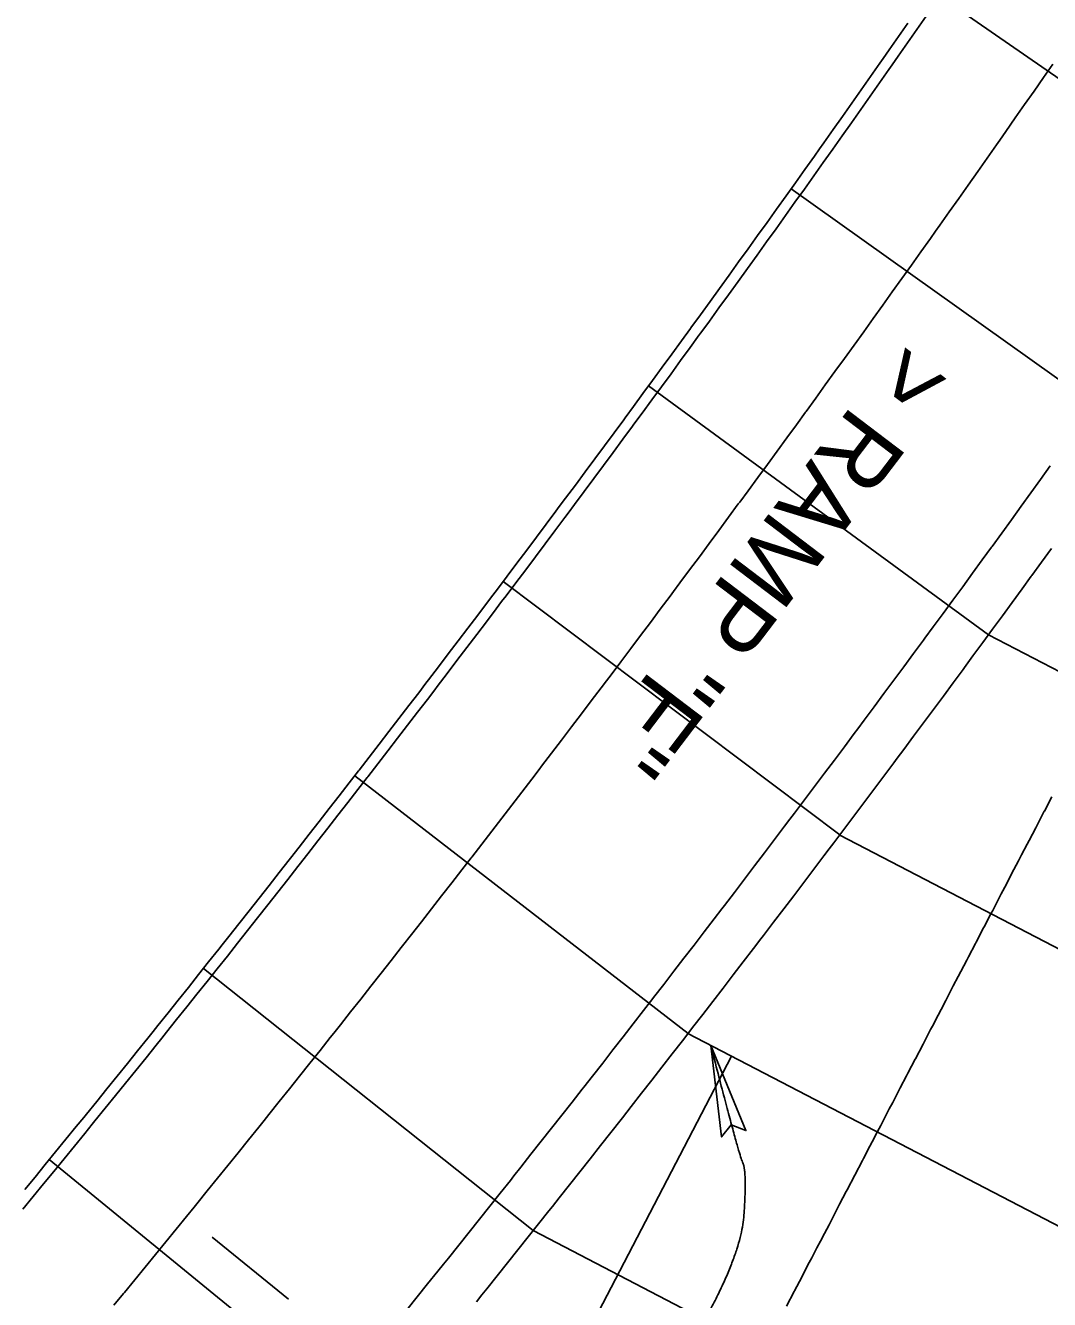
# Model space of a CAD drawing. Extents: x 2145147 to 2158018, y 137519 to 148068.
# Drawn here: x 2150427.2 to 2150489.6, y 143886.4 to 143964 of the extents above; entities that cross this region are included whole.
import ezdxf

# ---------------------------------------------------------------- set-up
doc = ezdxf.new("R2010")
doc.units = 0
for name, color, linetype in [('PR_Align_Ramp_F', 7, 'Continuous'), ('PR_Align_Ramp_F_Label', 7, 'Continuous'), ('PR_Dimensions', 7, 'Continuous'), ('PR_Joint_Contraction', 7, 'Continuous'), ('PR_Joint_Long', 7, 'Continuous'), ('PR_Road_Concrete', 7, 'Continuous')]:
    doc.layers.add(name, color=color, linetype=linetype)

msp = doc.modelspace()

# ---------------------------------------------------------------- linework, layer by layer
at = {"layer": 'PR_Align_Ramp_F'}
msp.add_lwpolyline([(2150443.256, 143886.371), (2150438.6, 143890.156)], dxfattribs=at)
at = {"layer": 'PR_Dimensions'}
msp.add_lwpolyline([(2150468.976, 143901.836), (2150469.629, 143896.26), (2150470.211, 143897.005), (2150471.112, 143896.649)], close=True, dxfattribs=at)
msp.add_open_spline([(2150468.143, 143884.29), (2150470.819, 143888.915), (2150471.175, 143894.152), (2150470.668, 143895.218), (2150468.976, 143901.836)], degree=2, dxfattribs=at)
at = {"layer": 'PR_Joint_Contraction'}
for p, q in [((2150503.472, 143951.523), (2150482.38, 143966.149)), ((2150494.767, 143939.143), (2150473.867, 143954.043)), ((2150485.885, 143926.855), (2150465.182, 143942.027)), ((2150476.825, 143914.661), (2150456.322, 143930.103)), ((2150485.885, 143926.856), (2150509.818, 143914.4)), ((2150467.586, 143902.559), (2150447.287, 143918.268)), ((2150476.826, 143914.66), (2150502.893, 143901.094)), ((2150458.166, 143890.552), (2150438.076, 143906.526)), ((2150467.585, 143902.56), (2150495.968, 143887.788)), ((2150448.565, 143878.639), (2150428.687, 143894.877)), ((2150458.166, 143890.552), (2150489.043, 143874.482))]:
    msp.add_line(p, q, dxfattribs=at)
at = {"layer": 'PR_Joint_Long'}
msp.add_line((2150449.468, 143861.259), (2150470.243, 143901.177), dxfattribs=at)
for points in [[(2150489.798, 143961.637), (2150489.229, 143960.817), (2150488.659, 143959.997), (2150488.089, 143959.178), (2150487.518, 143958.359), (2150486.946, 143957.541), (2150486.575, 143957.01), (2150486.374, 143956.723), (2150485.801, 143955.906), (2150485.227, 143955.089), (2150484.652, 143954.272), (2150484.077, 143953.457), (2150483.501, 143952.641), (2150482.924, 143951.826), (2150482.665, 143951.46), (2150482.347, 143951.012), (2150481.769, 143950.198), (2150481.19, 143949.385), (2150480.611, 143948.572), (2150480.03, 143947.76), (2150479.449, 143946.948), (2150478.868, 143946.137), (2150478.721, 143945.933), (2150478.285, 143945.326), (2150477.702, 143944.516), (2150477.119, 143943.706), (2150476.534, 143942.897), (2150475.949, 143942.088), (2150475.363, 143941.28), (2150474.776, 143940.472), (2150474.745, 143940.429), (2150474.189, 143939.665), (2150473.601, 143938.858), (2150473.012, 143938.052), (2150472.423, 143937.246), (2150471.833, 143936.441), (2150471.242, 143935.636), (2150470.736, 143934.949), (2150470.651, 143934.833), (2150470.058, 143934.029), (2150469.465, 143933.226), (2150468.872, 143932.423), (2150468.277, 143931.621), (2150467.682, 143930.82), (2150467.086, 143930.018), (2150466.695, 143929.493), (2150466.49, 143929.218), (2150465.893, 143928.418), (2150465.295, 143927.619), (2150464.697, 143926.82), (2150464.097, 143926.021), (2150463.497, 143925.223), (2150462.897, 143924.426), (2150462.622, 143924.061), (2150462.296, 143923.629), (2150461.694, 143922.833), (2150461.091, 143922.037), (2150460.487, 143921.242), (2150459.883, 143920.447), (2150459.279, 143919.653), (2150458.673, 143918.859), (2150458.516, 143918.654), (2150458.067, 143918.066), (2150457.46, 143917.274), (2150456.853, 143916.482), (2150456.244, 143915.69), (2150455.635, 143914.899), (2150455.026, 143914.108), (2150454.415, 143913.318), (2150454.378, 143913.271), (2150453.804, 143912.529), (2150453.193, 143911.74), (2150452.58, 143910.952), (2150451.967, 143910.164), (2150451.354, 143909.377), (2150450.739, 143908.59), (2150450.208, 143907.911), (2150450.124, 143907.804), (2150449.508, 143907.018), (2150448.892, 143906.233), (2150448.275, 143905.448), (2150447.657, 143904.664), (2150447.038, 143903.881), (2150446.419, 143903.098), (2150446.007, 143902.578), (2150445.799, 143902.316), (2150445.178, 143901.533), (2150444.557, 143900.752), (2150443.935, 143899.971), (2150443.312, 143899.191), (2150442.689, 143898.411), (2150442.065, 143897.632), (2150441.774, 143897.269), (2150441.441, 143896.854), (2150440.815, 143896.075), (2150440.189, 143895.298), (2150439.562, 143894.521), (2150438.935, 143893.744), (2150438.307, 143892.968), (2150437.678, 143892.193), (2150437.51, 143891.986), (2150437.049, 143891.418), (2150436.419, 143890.644), (2150435.788, 143889.87), (2150435.156, 143889.097), (2150434.524, 143888.324), (2150433.891, 143887.552), (2150433.258, 143886.781), (2150433.215, 143886.728), (2150432.624, 143886.01)], [(2150489.652, 143937.153), (2150489.062, 143936.333), (2150488.471, 143935.514), (2150487.88, 143934.695), (2150487.287, 143933.876), (2150486.694, 143933.058), (2150486.102, 143932.242), (2150486.067, 143932.195), (2150485.506, 143931.423), (2150484.911, 143930.607), (2150484.315, 143929.791), (2150483.718, 143928.975), (2150483.121, 143928.16), (2150482.523, 143927.346), (2150482.012, 143926.651), (2150481.923, 143926.53), (2150481.325, 143925.718), (2150480.724, 143924.905), (2150480.124, 143924.093), (2150479.522, 143923.281), (2150478.92, 143922.47), (2150478.317, 143921.66), (2150477.921, 143921.128), (2150477.712, 143920.847), (2150477.108, 143920.039), (2150476.503, 143919.23), (2150475.897, 143918.421), (2150475.291, 143917.613), (2150474.684, 143916.805), (2150474.077, 143915.999), (2150473.797, 143915.628), (2150473.466, 143915.19), (2150472.858, 143914.385), (2150472.248, 143913.58), (2150471.637, 143912.775), (2150471.025, 143911.97), (2150470.413, 143911.166), (2150469.801, 143910.365), (2150469.64, 143910.154), (2150469.186, 143909.56), (2150468.572, 143908.758), (2150467.957, 143907.956), (2150467.342, 143907.155), (2150466.725, 143906.354), (2150466.108, 143905.554), (2150465.492, 143904.756), (2150465.451, 143904.704), (2150464.872, 143903.955), (2150464.253, 143903.157), (2150463.633, 143902.359), (2150463.012, 143901.561), (2150462.391, 143900.764), (2150461.769, 143899.968), (2150461.233, 143899.283), (2150461.145, 143899.17), (2150460.523, 143898.377), (2150459.899, 143897.582), (2150459.274, 143896.788), (2150458.649, 143895.994), (2150458.023, 143895.201), (2150457.397, 143894.409), (2150456.98, 143893.883), (2150456.767, 143893.615), (2150456.14, 143892.825), (2150455.511, 143892.034), (2150454.882, 143891.244), (2150454.252, 143890.454), (2150453.621, 143889.665), (2150452.99, 143888.877), (2150452.695, 143888.509), (2150452.356, 143888.087), (2150451.724, 143887.3), (2150451.09, 143886.513), (2150450.456, 143885.727)], [(2150489.717, 143932.116), (2150489.122, 143931.296), (2150488.527, 143930.476), (2150488.495, 143930.433), (2150487.931, 143929.657), (2150487.334, 143928.838), (2150486.737, 143928.02), (2150486.139, 143927.203), (2150485.54, 143926.386), (2150484.94, 143925.569), (2150484.427, 143924.871), (2150484.34, 143924.753), (2150483.739, 143923.937), (2150483.137, 143923.122), (2150482.535, 143922.308), (2150481.932, 143921.494), (2150481.328, 143920.68), (2150480.723, 143919.868), (2150480.326, 143919.334), (2150480.118, 143919.055), (2150479.512, 143918.243), (2150478.905, 143917.432), (2150478.298, 143916.621), (2150477.69, 143915.811), (2150477.081, 143915.001), (2150476.471, 143914.192), (2150476.192, 143913.821), (2150475.861, 143913.383), (2150475.25, 143912.575), (2150474.638, 143911.768), (2150474.026, 143910.96), (2150473.413, 143910.154), (2150472.799, 143909.348), (2150472.185, 143908.542), (2150472.025, 143908.333), (2150471.569, 143907.737), (2150470.954, 143906.933), (2150470.337, 143906.129), (2150469.72, 143905.326), (2150469.102, 143904.523), (2150468.483, 143903.721), (2150467.864, 143902.919), (2150467.826, 143902.87), (2150467.244, 143902.118), (2150466.623, 143901.317), (2150466.001, 143900.517), (2150465.379, 143899.718), (2150464.756, 143898.919), (2150464.133, 143898.12), (2150463.594, 143897.432), (2150463.508, 143897.322), (2150462.884, 143896.525), (2150462.258, 143895.728), (2150461.632, 143894.932), (2150461.004, 143894.136), (2150460.377, 143893.341), (2150459.748, 143892.547), (2150459.331, 143892.019), (2150459.119, 143891.752), (2150458.489, 143890.959), (2150457.859, 143890.166), (2150457.228, 143889.374), (2150456.596, 143888.582), (2150455.963, 143887.79), (2150455.33, 143887), (2150455.035, 143886.632), (2150454.696, 143886.209)], [(2150489.747, 143916.991), (2150489.29, 143916.114), (2150489.285, 143916.104), (2150488.824, 143915.217), (2150488.766, 143915.106), (2150488.362, 143914.33), (2150488.241, 143914.098), (2150487.9, 143913.443), (2150487.716, 143913.09), (2150487.439, 143912.556), (2150487.192, 143912.082), (2150486.977, 143911.669), (2150486.667, 143911.074), (2150486.515, 143910.782), (2150486.143, 143910.066), (2150486.054, 143909.895), (2150485.618, 143909.058), (2150485.592, 143909.008), (2150485.13, 143908.12), (2150485.093, 143908.05), (2150484.669, 143907.233), (2150484.569, 143907.042), (2150484.207, 143906.346), (2150484.044, 143906.033), (2150483.745, 143905.459), (2150483.519, 143905.025), (2150483.284, 143904.572), (2150482.995, 143904.017), (2150482.822, 143903.685), (2150482.47, 143903.009), (2150482.36, 143902.798), (2150481.946, 143902.001), (2150481.899, 143901.911), (2150481.437, 143901.024), (2150481.421, 143900.993), (2150480.975, 143900.137), (2150480.896, 143899.985), (2150480.514, 143899.25), (2150480.372, 143898.977), (2150480.052, 143898.363), (2150479.847, 143897.969), (2150479.59, 143897.476), (2150479.322, 143896.961), (2150479.129, 143896.589), (2150478.798, 143895.953), (2150478.667, 143895.702), (2150478.273, 143894.945), (2150478.205, 143894.815), (2150477.749, 143893.937), (2150477.744, 143893.928), (2150477.282, 143893.041), (2150477.224, 143892.929), (2150476.82, 143892.154), (2150476.699, 143891.921), (2150476.359, 143891.266), (2150476.175, 143890.913), (2150475.897, 143890.379), (2150475.65, 143889.905), (2150475.435, 143889.492), (2150475.125, 143888.897), (2150474.974, 143888.605), (2150474.601, 143887.889), (2150474.512, 143887.718), (2150474.076, 143886.881), (2150474.05, 143886.831), (2150473.589, 143885.944)]]:
    msp.add_lwpolyline(points, dxfattribs=at)
at = {"layer": 'PR_Road_Concrete'}
for points in [[(2150482.091, 143964.565), (2150481.525, 143963.751), (2150480.958, 143962.938), (2150480.39, 143962.125), (2150480.022, 143961.598), (2150479.822, 143961.313), (2150479.253, 143960.502), (2150478.683, 143959.69), (2150478.112, 143958.88), (2150477.541, 143958.07), (2150476.969, 143957.26), (2150476.397, 143956.451), (2150476.138, 143956.087), (2150475.823, 143955.642), (2150475.249, 143954.834), (2150474.674, 143954.027), (2150474.099, 143953.219), (2150473.523, 143952.413), (2150472.946, 143951.607), (2150472.368, 143950.801), (2150472.223, 143950.598), (2150471.79, 143949.996), (2150471.211, 143949.191), (2150470.631, 143948.387), (2150470.051, 143947.584), (2150469.47, 143946.781), (2150468.888, 143945.978), (2150468.305, 143945.176), (2150468.274, 143945.133), (2150467.722, 143944.374), (2150467.138, 143943.573), (2150466.554, 143942.773), (2150465.968, 143941.973), (2150465.382, 143941.173), (2150464.796, 143940.374), (2150464.294, 143939.692), (2150464.208, 143939.576), (2150463.62, 143938.778), (2150463.031, 143937.98), (2150462.442, 143937.183), (2150461.852, 143936.387), (2150461.261, 143935.591), (2150460.669, 143934.796), (2150460.281, 143934.274), (2150460.077, 143934.001), (2150459.484, 143933.206), (2150458.89, 143932.412), (2150458.296, 143931.619), (2150457.701, 143930.826), (2150457.105, 143930.034), (2150456.509, 143929.242), (2150456.236, 143928.88), (2150455.912, 143928.451), (2150455.314, 143927.66), (2150454.716, 143926.87), (2150454.116, 143926.08), (2150453.517, 143925.291), (2150452.916, 143924.502), (2150452.315, 143923.714), (2150452.159, 143923.51), (2150451.713, 143922.927), (2150451.11, 143922.14), (2150450.507, 143921.353), (2150449.903, 143920.567), (2150449.298, 143919.782), (2150448.693, 143918.997), (2150448.087, 143918.212), (2150448.05, 143918.164), (2150447.48, 143917.428), (2150446.873, 143916.645), (2150446.265, 143915.862), (2150445.656, 143915.08), (2150445.046, 143914.298), (2150444.436, 143913.517), (2150443.909, 143912.843), (2150443.825, 143912.736), (2150443.214, 143911.956), (2150442.602, 143911.176), (2150441.989, 143910.397), (2150441.375, 143909.619), (2150440.761, 143908.84), (2150440.146, 143908.063), (2150439.737, 143907.547), (2150439.531, 143907.286), (2150438.914, 143906.51), (2150438.297, 143905.734), (2150437.68, 143904.958), (2150437.062, 143904.184), (2150436.443, 143903.409), (2150435.823, 143902.635), (2150435.534, 143902.275), (2150435.203, 143901.862), (2150434.582, 143901.09), (2150433.96, 143900.318), (2150433.338, 143899.546), (2150432.715, 143898.775), (2150432.091, 143898.004), (2150431.467, 143897.235), (2150431.3, 143897.029), (2150430.842, 143896.465), (2150430.216, 143895.696), (2150429.59, 143894.928), (2150428.962, 143894.16), (2150428.335, 143893.393), (2150427.706, 143892.626), (2150427.077, 143891.86)], [(2150480.978, 143964.132), (2150480.411, 143963.319), (2150479.844, 143962.507), (2150479.475, 143961.981), (2150479.276, 143961.696), (2150478.707, 143960.885), (2150478.138, 143960.074), (2150477.567, 143959.264), (2150476.996, 143958.454), (2150476.425, 143957.645), (2150475.853, 143956.836), (2150475.595, 143956.472), (2150475.28, 143956.028), (2150474.706, 143955.22), (2150474.131, 143954.413), (2150473.556, 143953.607), (2150472.98, 143952.801), (2150472.404, 143951.995), (2150471.827, 143951.19), (2150471.681, 143950.987), (2150471.249, 143950.385), (2150470.67, 143949.581), (2150470.091, 143948.777), (2150469.511, 143947.974), (2150468.93, 143947.172), (2150468.348, 143946.37), (2150467.766, 143945.568), (2150467.735, 143945.525), (2150467.183, 143944.767), (2150466.6, 143943.966), (2150466.015, 143943.166), (2150465.43, 143942.367), (2150464.845, 143941.568), (2150464.258, 143940.769), (2150463.757, 143940.087), (2150463.671, 143939.971), (2150463.084, 143939.174), (2150462.495, 143938.377), (2150461.906, 143937.58), (2150461.316, 143936.784), (2150460.726, 143935.989), (2150460.135, 143935.194), (2150459.746, 143934.672), (2150459.543, 143934.399), (2150458.95, 143933.605), (2150458.357, 143932.812), (2150457.763, 143932.019), (2150457.168, 143931.227), (2150456.573, 143930.435), (2150455.977, 143929.644), (2150455.703, 143929.281), (2150455.38, 143928.853), (2150454.782, 143928.062), (2150454.184, 143927.273), (2150453.585, 143926.484), (2150452.986, 143925.695), (2150452.386, 143924.907), (2150451.785, 143924.119), (2150451.629, 143923.915), (2150451.183, 143923.332), (2150450.581, 143922.545), (2150449.978, 143921.759), (2150449.374, 143920.974), (2150448.77, 143920.189), (2150448.165, 143919.404), (2150447.559, 143918.62), (2150447.522, 143918.572), (2150446.953, 143917.837), (2150446.346, 143917.054), (2150445.738, 143916.271), (2150445.13, 143915.489), (2150444.521, 143914.708), (2150443.911, 143913.927), (2150443.384, 143913.254), (2150443.301, 143913.147), (2150442.689, 143912.367), (2150442.078, 143911.588), (2150441.465, 143910.81), (2150440.852, 143910.031), (2150440.238, 143909.254), (2150439.624, 143908.477), (2150439.215, 143907.961), (2150439.008, 143907.7), (2150438.392, 143906.924), (2150437.776, 143906.149), (2150437.159, 143905.374), (2150436.541, 143904.6), (2150435.922, 143903.826), (2150435.303, 143903.052), (2150435.014, 143902.693), (2150434.683, 143902.28), (2150434.062, 143901.508), (2150433.441, 143900.736), (2150432.819, 143899.965), (2150432.196, 143899.194), (2150431.573, 143898.424), (2150430.949, 143897.655), (2150430.782, 143897.449), (2150430.324, 143896.886), (2150429.699, 143896.117), (2150429.073, 143895.349), (2150428.446, 143894.582), (2150427.819, 143893.815), (2150427.191, 143893.049)]]:
    msp.add_lwpolyline(points, dxfattribs=at)

# ---------------------------------------------------------------- texts
at = {"layer": 'PR_Align_Ramp_F_Label'}
msp.add_text('> RAMP "F"', height=4.3, rotation=232.75133, dxfattribs=at).set_placement((2150480.604, 143944.887))

doc.saveas('drawing.dxf')
